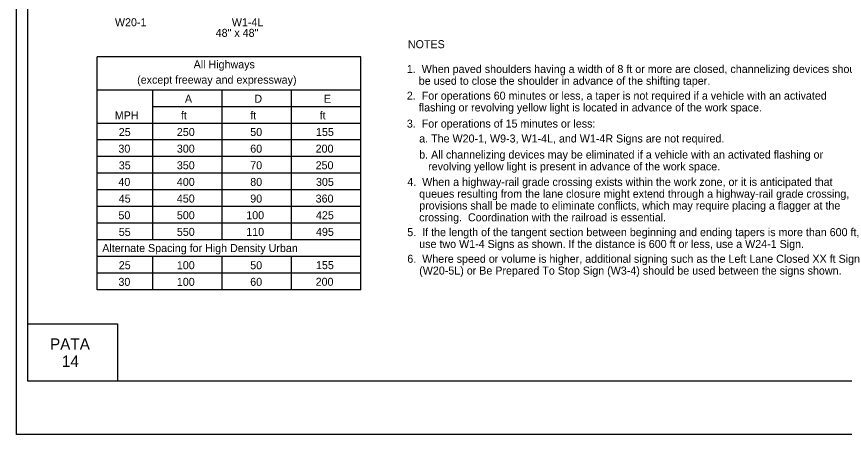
# Model space of a CAD drawing. Extents: x -14145 to -13662, y 30244 to 30661.
# Drawn here: x -13790.17 to -13768.45, y 30424.81 to 30435.78 of the extents above; entities that cross this region are included whole.
import ezdxf

# ---------------------------------------------------------------- set-up
doc = ezdxf.new("R2010")
doc.units = 0
for name, color, linetype in [('1', 7, 'Continuous'), ('10', 7, 'Continuous'), ('2', 7, 'Continuous'), ('3', 7, 'Continuous'), ('4', 7, 'Continuous'), ('61', 7, 'Continuous')]:
    doc.layers.add(name, color=color, linetype=linetype)

msp = doc.modelspace()

# ---------------------------------------------------------------- linework, layer by layer
at = {"layer": '1'}
for p, q in [((-13788.056, 30428.605), (-13788.056, 30434.724)), ((-13781.135, 30434.724), (-13788.056, 30434.724)), ((-13781.135, 30428.605), (-13781.135, 30434.724)), ((-13781.135, 30433.85), (-13788.057, 30433.85)), ((-13786.599, 30429.916), (-13786.599, 30433.85)), ((-13784.779, 30429.916), (-13784.779, 30433.85)), ((-13782.957, 30429.916), (-13782.957, 30433.85)), ((-13781.135, 30433.412), (-13786.599, 30433.412)), ((-13781.135, 30432.975), (-13788.057, 30432.975)), ((-13781.135, 30432.538), (-13788.057, 30432.538)), ((-13781.135, 30432.101), (-13788.057, 30432.101)), ((-13781.135, 30431.664), (-13788.057, 30431.664)), ((-13781.135, 30431.227), (-13788.057, 30431.227)), ((-13781.135, 30430.79), (-13788.057, 30430.79)), ((-13781.135, 30430.353), (-13788.057, 30430.353)), ((-13781.135, 30429.916), (-13788.057, 30429.916)), ((-13781.136, 30429.479), (-13788.057, 30429.479)), ((-13781.135, 30429.479), (-13788.057, 30429.479)), ((-13786.599, 30428.605), (-13786.599, 30429.479)), ((-13784.779, 30428.605), (-13784.779, 30429.479)), ((-13782.957, 30428.605), (-13782.957, 30429.479)), ((-13781.135, 30429.042), (-13788.057, 30429.042)), ((-13781.135, 30428.605), (-13788.056, 30428.605))]:
    msp.add_line(p, q, dxfattribs=at)
at = {"layer": '10'}
for p, q in [((-13789.874, 30426.207), (-13789.874, 30448.777)), ((-13789.874, 30427.707), (-13787.524, 30427.707)), ((-13787.524, 30427.707), (-13787.524, 30426.207)), ((-13758.422, 30426.207), (-13789.874, 30426.207))]:
    msp.add_line(p, q, dxfattribs=at)
at = {"layer": '61'}
msp.add_lwpolyline([(-13790.174, 30450.307), (-13757.174, 30450.307), (-13757.174, 30424.807), (-13790.174, 30424.807)], close=True, dxfattribs=at)

# ---------------------------------------------------------------- texts
at = {"layer": '2'}
for s, p in [('W20-1', (-13787.592, 30435.524)), ('W1-4L', (-13784.524, 30435.524)), ('48" x 48"', (-13784.948, 30435.246)), ('NOTES', (-13779.904, 30434.948)), ('1.  When paved shoulders having a width of 8 ft or more are closed, channelizing devices should', (-13779.931, 30434.297)), ('    be used to close the shoulder in advance of the shifting taper.', (-13779.931, 30433.987)), ('A', (-13785.756, 30433.516)), ('D', (-13783.933, 30433.516)), ('E', (-13782.109, 30433.516)), ('2.  For operations 60 minutes or less, a taper is not required if a vehicle with an activated', (-13779.931, 30433.597)), ('    flashing or revolving yellow light is located in advance of the work space.', (-13779.931, 30433.287)), ('MPH', (-13787.596, 30433.079)), ('ft', (-13785.861, 30433.079)), ('ft', (-13784.04, 30433.079)), ('ft', (-13782.218, 30433.079)), ('3.  For operations of 15 minutes or less:', (-13779.931, 30432.863)), ('25', (-13787.491, 30432.642)), ('250', (-13785.967, 30432.643)), ('50', (-13784.041, 30432.643)), ('155', (-13782.316, 30432.643)), ('    a. The W20-1, W9-3, W1-4L, and W1-4R Signs are not required.', (-13779.919, 30432.472)), ('30', (-13787.501, 30432.205)), ('300', (-13785.967, 30432.206)), ('60', (-13784.041, 30432.206)), ('200', (-13782.325, 30432.206)), ('    b. All channelizing devices may be eliminated if a vehicle with an activated flashing or', (-13779.919, 30432.05)), ('35', (-13787.491, 30431.768)), ('350', (-13785.967, 30431.769)), ('70', (-13784.041, 30431.769)), ('250', (-13782.325, 30431.769)), ('       revolving yellow light is present in advance of the work space.', (-13779.919, 30431.74)), ('40', (-13787.501, 30431.331)), ('400', (-13785.967, 30431.332)), ('80', (-13784.041, 30431.332)), ('305', (-13782.316, 30431.332)), ('4.  When a highway-rail grade crossing exists within the work zone, or it is anticipated that', (-13779.919, 30431.332)), ('    queues resulting from the lane closure might extend through a highway-rail grade crossing,', (-13779.919, 30431.022)), ('45', (-13787.491, 30430.894)), ('450', (-13785.967, 30430.895)), ('90', (-13784.041, 30430.895)), ('360', (-13782.325, 30430.895)), ('    provisions shall be made to eliminate conflicts, which may require placing a flagger at the', (-13779.919, 30430.712)), ('50', (-13787.5, 30430.457)), ('500', (-13785.967, 30430.458)), ('100', (-13784.146, 30430.458)), ('425', (-13782.316, 30430.458)), ('    crossing.  Coordination with the railroad is essential.', (-13779.919, 30430.402)), ('55', (-13787.491, 30430.019)), ('550', (-13785.967, 30430.021)), ('110', (-13784.146, 30430.021)), ('495', (-13782.316, 30430.021)), ('5.  If the length of the tangent section between beginning and ending tapers is more than 600 ft, ', (-13779.919, 30430.013)), ('    use two W1-4 Signs as shown. If the distance is 600 ft or less, use a W24-1 Sign.', (-13779.919, 30429.703)), ('6.  Where speed or volume is higher, additional signing such as the Left Lane Closed XX ft Sign ', (-13779.919, 30429.314)), ('25', (-13787.491, 30429.145)), ('100', (-13785.967, 30429.145)), ('50', (-13784.041, 30429.145)), ('155', (-13782.316, 30429.147)), ('    (W20-5L) or Be Prepared To Stop Sign (W3-4) should be used between the signs shown.', (-13779.919, 30429.004)), ('30', (-13787.5, 30428.708)), ('100', (-13785.967, 30428.708)), ('60', (-13784.041, 30428.708)), ('200', (-13782.325, 30428.71))]:
    msp.add_text(s, height=0.21, dxfattribs=at).set_placement(p)
at = {"layer": '3'}
for s, height, p in [('All Highways', 0.20979, (-13785.526, 30434.419)), ('(except freeway and expressway)', 0.21, (-13787.009, 30434.016)), ('Alternate Spacing for High Density Urban', 0.20979, (-13787.924, 30429.596))]:
    msp.add_text(s, height=height, dxfattribs=at).set_placement(p)
at = {"layer": '4'}
for s, p in [('PATA', (-13789.296, 30427.03)), ('14', (-13788.983, 30426.58))]:
    msp.add_text(s, height=0.3, dxfattribs=at).set_placement(p)

doc.saveas('drawing.dxf')
